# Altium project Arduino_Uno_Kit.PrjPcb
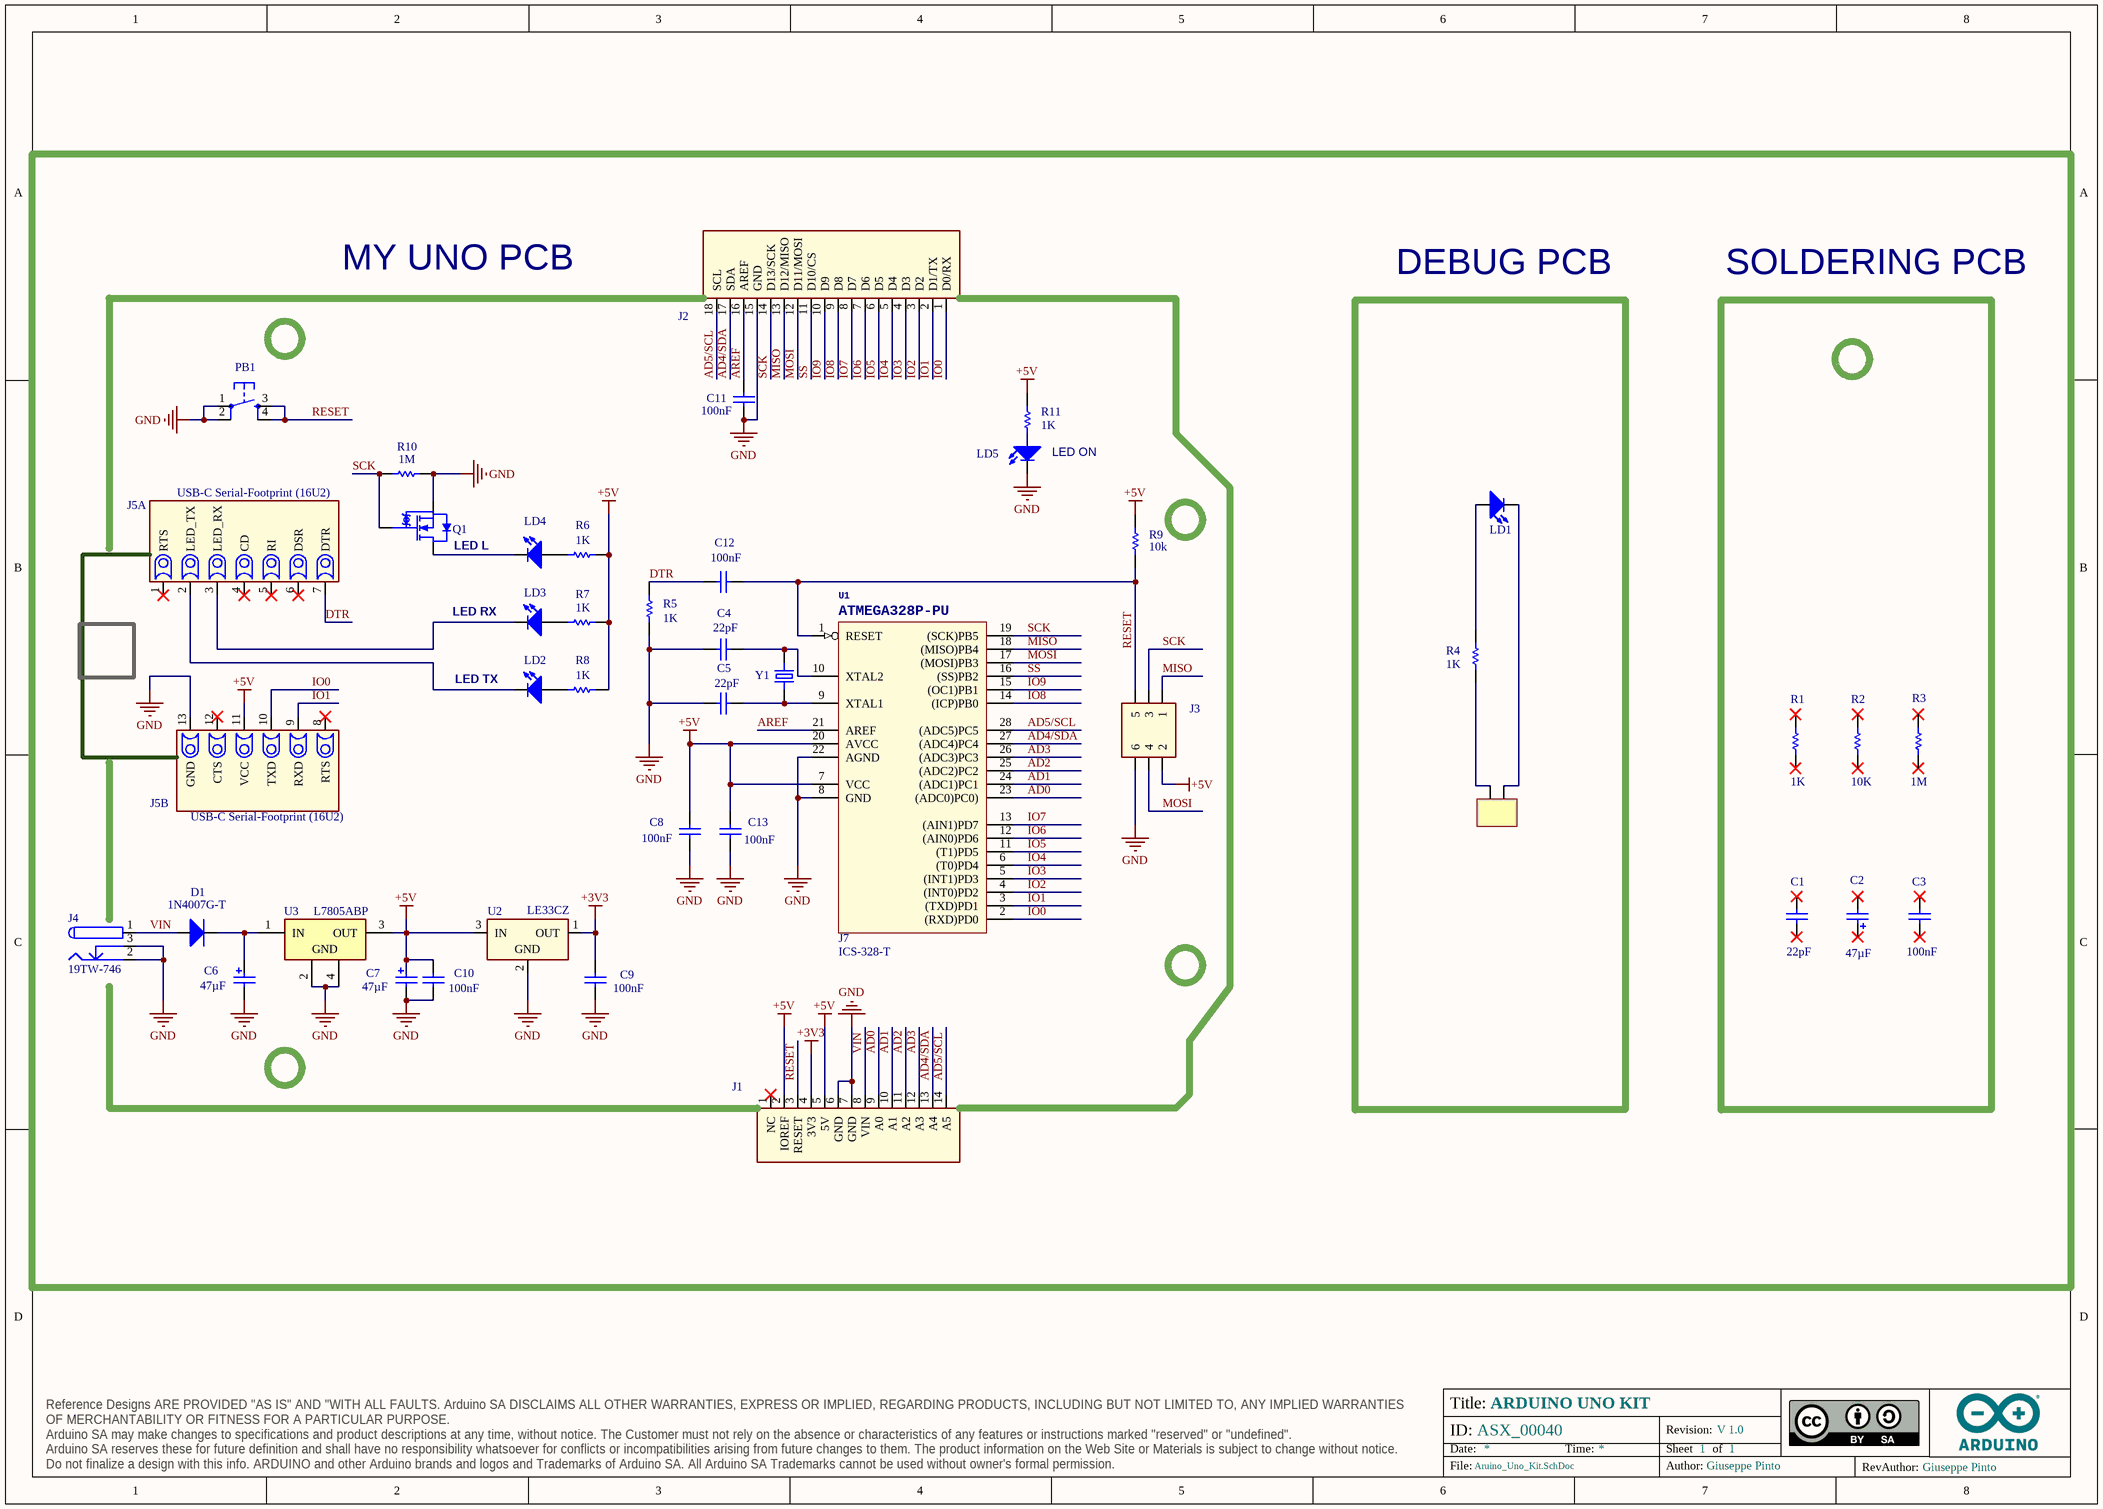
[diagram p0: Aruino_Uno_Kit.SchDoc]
Title: _; THICKNESS: 1.6mm; THD: _; TBD: _; TABS: _; SOLDERMASK_TOP: X; SOLDERMASK_PEELABLE_TOP: _; SOLDERMASK_PEELABLE_COLOR: _; SOLDERMASK_PEELABLE_BOTTOM: _; SOLDERMASK_COLOR: GREEN ARDUINO; SOLDERMASK_BOTTOM: X; SN/PB: _; SMD: _; SKU: ASX00040; SILK_TOP: X; SILK_COLOR: WHITE; SILK_BOTTOM: X; SCORING: _; RIGID/FLEX: _; RIGID: X; Revision: V 1.0; PRESSFIT: _; POLYMIDE: _; PCB_SIZE: 68.581X53.323mm; PANEL_SIZE: 293X164mm; PANEL_REQUESTED: X; PANEL_PROVIDED: _; PANEL_NO: _; N_FIGURES: 12; NLAYERS: 2; NI/AU: _; MIN_TRACK_WIDTH_OUTER: 0.127mm; MIN_TRACK_WIDTH_INNER: 0.127mm; MIN_INSULATION_OUTER: 0.127mm; MIN_INSULATION_INNER: 0.127mm; MILLING: X; IPCNA: X; IPC3: _; IPC2: _; IPC1: _; ID: _; HOLE_TOP_BOTTOM: X; HAL_LF: _; HAL: X; FR4_HTG: _; FR4: X; FLEX: _; FINISH_TBD: _; ENIG: _; EDGE_PLATING: _; DRILLS_SOLDER_FILLING: _; DRILLS_SLOT: _; DRILLS_RESIN_FILLING: _; DRILLS_PRESSFIT: _; DRILLS_LASER: _; DRILLS_FULL: X; DRILLS_COPPER_FILLING: _; DRILLS_BURIED: _; DRILLS_BLIND: _; BGA: _; Author: Giuseppe Pinto; ADJUSTMENTS: _
1 sheet, 43 parts. Net scope: global (net labels, ports and power ports of the same name join across sheets).
Board files: Arduino_Uno_Kit.PcbDoc, Arduino_Uno_Kit_Panel.PcbDoc

## Sheet Aruino_Uno_Kit.SchDoc: ARDUINO UNO KIT
size A3; Author: Giuseppe Pinto; CompanyName: Arduino; Engineer: Giuseppe Pinto; DocumentNumber: ASX_00040; Revision: V 1.0; SheetNumber: 1; SheetTotal: 1; RevAuthor: Giuseppe Pinto

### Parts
C1  value 22pF  [TS170R1H220JSANB0R]  (hidden comment: TS170R1H220JSANB0R)
C2  value 47µF  [EKF476M1EE05TU]  (hidden comment: EKF476M1EE05TU)
C3  value 100nF  [B32529C0104J289]  (hidden comment: B32529C0104J289)
C4  value 22pF  [TS170R1H220JSANB0R]  (hidden comment: TS170R1H220JSANB0R)
C5  value 22pF  [TS170R1H220JSANB0R]  (hidden comment: TS170R1H220JSANB0R)
C6  value 47µF  [EKF476M1EE05TU]  (hidden comment: EKF476M1EE05TU)
C7  value 47µF  [EKF476M1EE05TU]  (hidden comment: EKF476M1EE05TU)
C8  value 100nF  [B32529C0104J289]  (hidden comment: B32529C0104J289)
C9  value 100nF  [B32529C0104J289]  (hidden comment: B32529C0104J289)
C10  value 100nF  [B32529C0104J289]  (hidden comment: B32529C0104J289)
C11  value 100nF  [B32529C0104J289]  (hidden comment: B32529C0104J289)
C12  value 100nF  [B32529C0104J289]  (hidden comment: B32529C0104J289)
C13  value 100nF  [B32529C0104J289]  (hidden comment: B32529C0104J289)
D1  1N4007G-T  [1N4007G-T-Footprint-1]
J1  20TW-995  [1X14-CUSTOM]  (value not drawn)
J2  20TW-994  [1X18-CUSTOM]  (value not drawn)
J3  PH2-06-UA  [2X03]  (value not drawn)
J4  19TW-746  [POWERSUPPLY_DC-21MM]
J5  USB-C Serial-Footprint (16U2)  [USB-C Serial-Footprint (16U2)]  (parts A,B of 2)  (no BOM)
J6  MK125002GO  [MK125002GO]  (value not drawn)
J7  ICS-328-T  [ICS-328-T-Footprint-1]
LD1  L-7104YD  [L314YD-Footprint-1]  (value not drawn)
LD2  L-7104YD  [L314YD-Footprint-1]  (value not drawn)
LD3  L-7104YD  [L314YD-Footprint-1]  (value not drawn)
LD4  L-7104YD  [L314YD-Footprint-1]  (value not drawn)
LD5  L-7104GD  [L314YD-Footprint-1]  (value not drawn)
PB1  TS21043-160B-5227260  [SW6X6]  (value not drawn)
Q1  2N7000BU  [SOT23]  (value not drawn)
R1  value 1K  [A5215]  (hidden comment: 2-1623930-9)
R2  value 10K  [A5213]  (hidden comment: 0-1623930-3)
R3  value 1M  [A5217]  (hidden comment: 3-1623930-5)
R4  value 1K  [A5215]  (hidden comment: 2-1623930-9)
R5  value 1K  [A5215]  (hidden comment: 2-1623930-9)
R6  value 1K  [A5215]  (hidden comment: 2-1623930-9)
R7  value 1K  [A5215]  (hidden comment: 2-1623930-9)
R8  value 1K  [A5215]  (hidden comment: 2-1623930-9)
R9  value 10k  [A5213]  (hidden comment: 0-1623930-3)
R10  value 1M  [A5217]  (hidden comment: 3-1623930-5)
R11  value 1K  [A5215]  (hidden comment: 2-1623930-9)
U1  ATMEGA328P-PU  [DIL28-3]
U2  LE33CZ  [LE33CZ-TR/AP]
U3  L7805ABP  [TO220]
Y1  ECS-160-20-4X-DU  [ECS-160-20-4X-DU-Footprint-1]  (value not drawn)

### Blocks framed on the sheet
MY UNO PCB: C4-C13 D1 J1-J5 J7 LD2-LD5 PB1 Q1 R5-R11 U1-U3 Y1
DEBUG PCB: J6 LD1 R4
SOLDERING PCB: C1-C3 R1-R3

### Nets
+3V3: C9.1 J1.4(3V3) U2.1(OUT)
+5V: C7.2 C8.1 C10.1 C13.1 J1.2(IOREF) J1.5(5V) J3.2 J5.11(VCC) R6.1 R7.1 R8.1 R9.2 R11.1 U1.7(VCC) U1.20(AVCC) U2.3(IN) U3.3(OUT)
GND: C4.2 C5.2 C6.1 C7.1 C8.2 C9.2 C10.2 C11.2 C13.2 J1.6(GND) J1.7(GND) J2.15(GND) J3.6 J4.2 J4.3 J5.13(GND) LD5.C PB1.1 PB1.2 Q1.1(S) R5.2 R10.2 U1.8(GND) U1.22(AGND) U2.2(GND) U3.2(GND) U3.4(GND)
AD0: J1.9(A0) U1.23((ADC0)PC0))
AD1: J1.10(A1) U1.24((ADC1)PC1)
AD2: J1.11(A2) U1.25((ADC2)PC2)
AD3: J1.12(A3) U1.26((ADC3)PC3)
AD4/SDA: J1.13(A4) J2.17(SDA) U1.27((ADC4)PC4)
AD5/SCL: J1.14(A5) J2.18(SCL) U1.28((ADC5)PC5)
AREF: C11.1 J2.16(AREF) U1.21(AREF)
DTR: C12.2 J5.7(DTR) R5.1
IO0: J2.1(D0/RX) J5.10(TXD) U1.2((RXD)PD0)
IO1: J2.2(D1/TX) J5.9(RXD) U1.3((TXD)PD1)
IO2: J2.3(D2) U1.4((INT0)PD2)
IO3: J2.4(D3) U1.5((INT1)PD3)
IO4: J2.5(D4) U1.6((T0)PD4)
IO5: J2.6(D5) U1.11((T1)PD5)
IO6: J2.7(D6) U1.12((AIN0)PD6)
IO7: J2.8(D7) U1.13((AIN1)PD7)
IO8: J2.9(D8) U1.14((ICP)PB0)
IO9: J2.10(D9) U1.15((OC1)PB1)
MISO: J2.13(D12/MISO) J3.1 U1.18((MISO)PB4)
MOSI: J2.12(D11/MOSI) J3.4 U1.17((MOSI)PB3)
RESET: C12.1 J1.3(RESET) J3.5 PB1.3 PB1.4 R9.1 U1.1(RESET)
SCK: J2.14(D13/SCK) J3.3 Q1.2(G) R10.1 U1.19((SCK)PB5)
SS: J2.11(D10/CS) U1.16((SS)PB2)
VIN: D1.1 J1.8(VIN) J4.1
NetC4_1: C4.1 U1.10(XTAL2) Y1.2
NetC5_1: C5.1 U1.9(XTAL1) Y1.1
NetC6_2: C6.2 D1.2 U3.1(IN)
NetJ5_2: J5.2(LED_TX) LD2.C
NetJ5_3: J5.3(LED_RX) LD3.C
NetJ6_1: J6.1 R4.1
NetJ6_2: J6.2 LD1.C
NetLD1_A: LD1.A R4.2
NetLD2_A: LD2.A R8.2
NetLD3_A: LD3.A R7.2
NetLD4_A: LD4.A R6.2
NetLD4_C: LD4.C Q1.3(D)
NetLD5_A: LD5.A R11.2

Not connected (* = marked no-connect by the designer): C1 1* 2*; C2 1* 2*; C3 1* 2*; J1 1(NC)*; J5 1(RTS)* 4(CD)* 5(RI)* 6(DSR)* 8(RTS)* 12(CTS)*; R1 1* 2*; R2 1* 2*; R3 1* 2*

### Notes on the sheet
- LED ON
- (near Q1) LED L
- (near LD3) LED RX
- (near LD2) LED TX

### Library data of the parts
C1 C4 C5 = C0124-A.13: CAP THD 22pF 50V C0G 5%; Manufacturer: Suntan; Code Arduino: C0124
C2 C6 C7 = C0125-A.8: CAP ALUM POL THD 47uF 25V; Manufacturer: SAMXON; Tolerance: 20%; Code Arduino: C0125
C3 C8-C13 = C0127-A.6: CAP THD 100NF 63V POLIESTER; Manufacturer: EPCOS; Code Arduino: 0080; Tolerance: 5%
D1 = D0054-A.4: Diodes [1N4007]; Manufacturer: Panjit; Code Arduino: 0066; Voltage Rating (DC): 1kV
J1 = J0063-A.5: CONN STRIP F/1/D 14v SER.NERA s1pin; Code Arduino: 3649
J2 = J0035-A.8: CONN STRIP F/1/D 18v SER.NERA s1pin; Code Arduino: 3648
J3 = J0004-A.4: CONN Header Through Hole 6 position 0.100" (2.54mm); Manufacturer: Adam Tech; Code Arduino: 0114
J4 = J0236-A.3: CONN PWR JACK 2.1X5.5MM SOLDER; Manufacturer: 4UCON; Code Arduino: 0018
J5 = AF0006-A.8
J6 = J0012-A.7: CONN MORS.CS 2v p3,5 10A aLING.VER; Manufacturer: Adimpex; Code Arduino: 2341
J7 = J0044-A.1: CONN DIP 28 SOCKET; Manufacturer: Adam Tech; Code Arduino: 0064; Pitch: 2.54mm
LD1-LD4 = L0021-A.7: LED THD YELLOW DIFFUSED T-1, 3mm; Manufacturer: Kingbright; Code Arduino: L0021
LD5 = L0023-A.5: LED THD GREEN DIFFUSED T-1, 3mm; Manufacturer: Kingbright; Code Arduino: L0023
PB1 = B0002-A.6: PUSHBUTTON.6x6 CS Hatt0,7 NERO 160g; Code Arduino: 0089
Q1 = T0035-A.6: TRANSISTOR NMOS SMALL SIGNAL EFFECT 0.2A I(D) 1-ELEMENT; Manufacturer: Onsemi; Drain to Source Breakdown Voltage: 60V; Code Arduino: T0035; Rds On Max: 1.2; Device Type: Mosfet N-CH SMD
R1 R4-R8 R11 = R0221-A.13: RES FIXED THD 1K OHM 1/4W 5%; Manufacturer: TE connectivity; Power: 250mW
R2 R9 = R0226-A.10: RES THD 10K 1/4W 5%; Manufacturer: TE connectivity; Power: 250mW
R3 R10 = R0227-A.11: RES THD 1M OHM 1/4w  5%; Manufacturer: TE Connectivity; Power: 250mW
U1 = U0038-A.2: IC MICROCONTROLLER ATMEGA328P-PU; Manufacturer: Microchip; Device Type: MCU
U2 = U0246-A.6: IC REG LDO FIXED 3.3V, 0.2V DROPOUT TO-92-3; Manufacturer: STMicroelectronics; Power Supply Rejection Ratio (PSRR): 80db; Number of Outputs: 1; Max Input Voltage: 18V; Code Arduino: U0246; Polarity: Positive; Dropout Voltage: 2V; Max Output Current: 100mA; Quiescent Current: 1mA; Tolerance: 1%; Output Voltage: 3v3
U3 = U0239-A.4: IC REG LINEAR 5V 1.5A TO220AB; Manufacturer: STMicroelectronics; Output Configuration: Positive; Number of Regulators: 1; Max Input Voltage: 25V; Quiescent Current: 8mA; Tolerance: 5%; Min Input Voltage: 7V; Dropout Voltage: 2V; Output Type: Fixed; Power Supply Rejection Ratio (PSRR): 62dB; Code Arduino: U0239
Y1 = X0004-A.3: CRYSTAL 16.0000MHZ 20PF THD; Manufacturer: ECS; Code Arduino: 0019

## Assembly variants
SL-ASX00040: not fitted +5V DTR GND IO0 IO1 J? LED_RX LED_TX MISO MOSI PB_4 PB_5 PB_6 PB_7 RESET SCK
